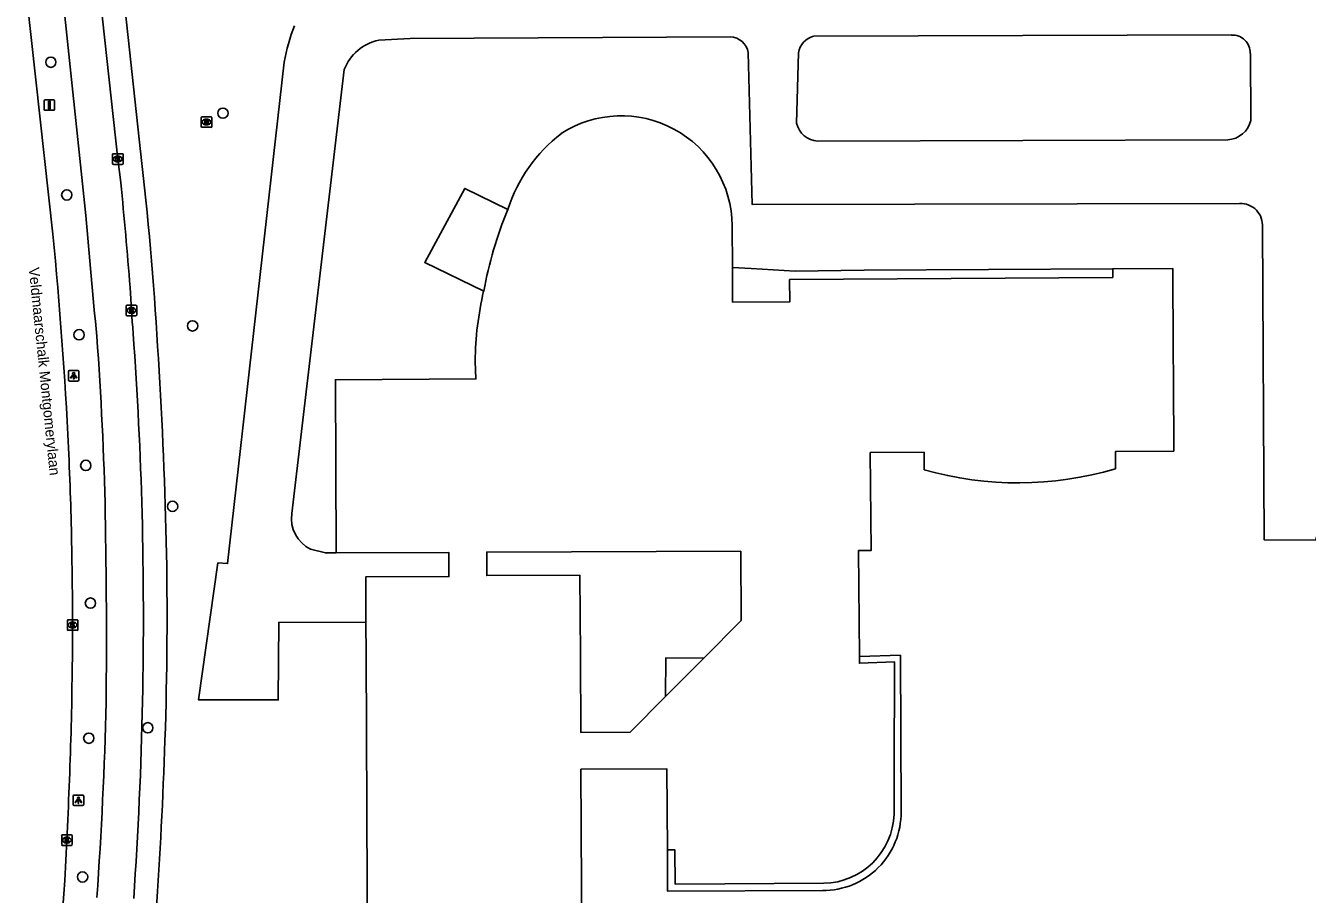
# Model space of a CAD drawing. Extents: x 161243 to 161752, y 384138 to 384885.
# Drawn here: x 161309.8 to 161431.6, y 384749.3 to 384831.8 of the extents above; entities that cross this region are included whole.
import ezdxf

# ---------------------------------------------------------------- set-up
doc = ezdxf.new("R2010")
doc.units = 0
for name, color, linetype in [('IMGEO_Boom', 7, 'Continuous'), ('IMGEO_Fietspad_gesloten', 7, 'Continuous'), ('IMGEO_Kolk', 7, 'Continuous'), ('IMGEO_Lichtpunt', 7, 'Continuous'), ('IMGEO_Openbare_ruimte_label', 7, 'Continuous'), ('IMGEO_OVBaan_gesloten', 7, 'Continuous'), ('IMGEO_Pand', 7, 'Continuous'), ('IMGEO_Pand_overbouw', 7, 'Continuous'), ('IMGEO_Rijbaan_lokaal_open', 7, 'Continuous'), ('IMGEO_Rioolput', 7, 'Continuous'), ('IMGEO_Verkeersbordpaal', 7, 'Continuous'), ('IMGEO_Voetpad_open', 7, 'Continuous')]:
    doc.layers.add(name, color=color, linetype=linetype)

msp = doc.modelspace()

# ---------------------------------------------------------------- linework, layer by layer
at = {"layer": 'IMGEO_Boom'}
for centre in [(161312.17, 384828.34), (161328.52, 384823.5), (161313.68, 384815.73), (161314.85, 384802.46), (161325.64, 384803.3), (161315.49, 384790.05), (161323.74, 384786.16), (161315.93, 384776.97), (161321.38, 384765.13), (161315.77, 384764.14), (161315.19, 384750.96)]:
    msp.add_circle(centre, 0.489, dxfattribs=at)
at = {"layer": 'IMGEO_Fietspad_gesloten'}
for points in [[(161313.17, 384835.74), (161315.49, 384813.78)], [(161318.81, 384816.9), (161318.53, 384819.14), (161316.84, 384834.53), (161316.67, 384836.2)]]:
    msp.add_lwpolyline(points, dxfattribs=at)
for centre, radius, start, end in [((160915.15, 384775.95), 405.73, 4.3808, 5.7921), ((162556.31, 384921.4), 1245.48, 184.95705, 185.48677), ((161677.13, 384828.87), 358.11, 183.51, 184.2089), ((160980.58, 384777.83), 336.85, 1.2915, 4.1673), ((160941.96, 384775.2), 379.02, 1.5556, 4.1435), ((160679.21, 384773.53), 638.24, 359.465, 1.06774), ((160926.58, 384775.69), 394.38, 358.8325, 1.4244), ((160906.46, 384777.92), 411.1, 355.9663, 358.557), ((160927.84, 384775.9), 393.13, 356.0636, 358.7984)]:
    msp.add_arc(centre, radius, start, end, dxfattribs=at)
at = {"layer": 'IMGEO_Kolk'}
for p, q in [((161318.03, 384818.71), (161318.03, 384819.57)), ((161318.11, 384819.64), (161318.96, 384819.64)), ((161318.52, 384819.42), (161318.54, 384819.42)), ((161318.54, 384818.86), (161318.52, 384818.86)), ((161319.03, 384819.57), (161319.03, 384818.71)), ((161318.96, 384818.64), (161318.11, 384818.64)), ((161319.34, 384804.33), (161319.34, 384805.18)), ((161319.41, 384805.26), (161320.26, 384805.26)), ((161320.26, 384804.26), (161319.41, 384804.26)), ((161319.85, 384804.48), (161319.82, 384804.48)), ((161319.83, 384805.04), (161319.85, 384805.04)), ((161320.34, 384805.18), (161320.34, 384804.33)), ((161313.74, 384774.46), (161313.74, 384775.31)), ((161313.82, 384775.39), (161314.67, 384775.39)), ((161314.23, 384775.17), (161314.26, 384775.17)), ((161314.74, 384775.31), (161314.74, 384774.46)), ((161314.67, 384774.39), (161313.82, 384774.39)), ((161314.25, 384774.61), (161314.23, 384774.61)), ((161313.2, 384754.03), (161313.2, 384754.88)), ((161313.27, 384754.96), (161314.12, 384754.96)), ((161313.68, 384754.74), (161313.71, 384754.74)), ((161313.71, 384754.18), (161313.68, 384754.18)), ((161314.2, 384754.88), (161314.2, 384754.03)), ((161314.12, 384753.96), (161313.27, 384753.96))]:
    msp.add_line(p, q, dxfattribs=at)
for points in [[(161318.03, 384818.71), (161318.03, 384819.57)], [(161318.11, 384819.64), (161318.96, 384819.64)], [(161318.35, 384819.34), (161318.48, 384819.34), (161318.48, 384819.19), (161318.6, 384819.34), (161318.77, 384819.34), (161318.62, 384819.19), (161318.78, 384818.94), (161318.62, 384818.94), (161318.54, 384819.11), (161318.48, 384819.04), (161318.48, 384818.94), (161318.35, 384818.94), (161318.35, 384819.34)], [(161319.03, 384819.57), (161319.03, 384818.71)], [(161318.96, 384818.64), (161318.11, 384818.64)], [(161319.34, 384804.33), (161319.34, 384805.18)], [(161319.41, 384805.26), (161320.26, 384805.26)], [(161320.26, 384804.26), (161319.41, 384804.26)], [(161319.66, 384804.96), (161319.78, 384804.96), (161319.78, 384804.81), (161319.91, 384804.96), (161320.08, 384804.96), (161319.93, 384804.81), (161320.08, 384804.56), (161319.93, 384804.56), (161319.85, 384804.72), (161319.78, 384804.66), (161319.78, 384804.56), (161319.66, 384804.56), (161319.66, 384804.96)], [(161320.34, 384805.18), (161320.34, 384804.33)], [(161313.74, 384774.46), (161313.74, 384775.31)], [(161313.82, 384775.39), (161314.67, 384775.39)], [(161314.06, 384775.09), (161314.19, 384775.09), (161314.19, 384774.94), (161314.32, 384775.09), (161314.48, 384775.09), (161314.33, 384774.94), (161314.49, 384774.69), (161314.33, 384774.69), (161314.25, 384774.85), (161314.19, 384774.78), (161314.19, 384774.69), (161314.06, 384774.69), (161314.06, 384775.09)], [(161314.74, 384775.31), (161314.74, 384774.46)], [(161314.67, 384774.39), (161313.82, 384774.39)], [(161313.2, 384754.03), (161313.2, 384754.88)], [(161313.27, 384754.96), (161314.12, 384754.96)], [(161313.52, 384754.66), (161313.64, 384754.66), (161313.64, 384754.5), (161313.77, 384754.66), (161313.93, 384754.66), (161313.79, 384754.51), (161313.94, 384754.26), (161313.79, 384754.26), (161313.7, 384754.42), (161313.64, 384754.35), (161313.64, 384754.26), (161313.52, 384754.26), (161313.52, 384754.66)], [(161314.2, 384754.88), (161314.2, 384754.03)], [(161314.12, 384753.96), (161313.27, 384753.96)]]:
    msp.add_lwpolyline(points, dxfattribs=at)
for centre, start, end in [((161318.11, 384819.57), 91.552, 178.448), ((161318.11, 384819.57), 91.552, 178.448), ((161318.11, 384818.72), 181.552, 268.448), ((161318.11, 384818.72), 181.552, 268.448), ((161318.96, 384819.57), 1.552, 88.448), ((161318.96, 384819.57), 1.552, 88.448), ((161318.96, 384818.72), 271.552, 358.448), ((161318.96, 384818.72), 271.552, 358.448), ((161319.41, 384805.18), 91.552, 178.448), ((161319.41, 384805.18), 91.552, 178.448), ((161319.41, 384804.33), 181.552, 268.448), ((161319.41, 384804.33), 181.552, 268.448), ((161320.26, 384805.18), 1.552, 88.448), ((161320.26, 384805.18), 1.552, 88.448), ((161320.26, 384804.33), 271.552, 358.448), ((161320.26, 384804.33), 271.552, 358.448), ((161313.82, 384775.31), 91.552, 178.448), ((161313.82, 384775.31), 91.552, 178.448), ((161314.67, 384775.31), 1.552, 88.448), ((161314.67, 384775.31), 1.552, 88.448), ((161313.82, 384774.46), 181.552, 268.448), ((161313.82, 384774.46), 181.552, 268.448), ((161314.67, 384774.46), 271.552, 358.448), ((161314.67, 384774.46), 271.552, 358.448), ((161313.27, 384754.88), 91.552, 178.448), ((161313.27, 384754.88), 91.552, 178.448), ((161314.12, 384754.88), 1.552, 88.448), ((161314.12, 384754.88), 1.552, 88.448), ((161313.27, 384754.03), 181.552, 268.448), ((161313.27, 384754.03), 181.552, 268.448), ((161314.12, 384754.03), 271.552, 358.448), ((161314.12, 384754.03), 271.552, 358.448)]:
    msp.add_arc(centre, 0.0765, start, end, dxfattribs=at)
for centre, major_axis, ratio, start_param, end_param in [((161318.52, 384819.14), (-0.387, 0.002), 0.722429, 4.712389, 7.853982), ((161318.54, 384819.14), (-0.39, 0.002), 0.717154, 1.570796, 4.712389), ((161319.82, 384804.76), (-0.387, 0.002), 0.722429, 4.712389, 7.853982), ((161319.85, 384804.76), (-0.39, 0.002), 0.717154, 1.570796, 4.712389), ((161314.23, 384774.89), (-0.387, 0.002), 0.722429, 4.712389, 7.853982), ((161314.25, 384774.89), (-0.39, 0.002), 0.717154, 1.570796, 4.712389), ((161313.68, 384754.46), (-0.387, 0.002), 0.722429, 4.712389, 7.853982), ((161313.71, 384754.46), (-0.39, 0.002), 0.717154, 1.570796, 4.712389)]:
    msp.add_ellipse(centre, major_axis=major_axis, ratio=ratio, start_param=start_param, end_param=end_param, dxfattribs=at)
at = {"layer": 'IMGEO_Lichtpunt'}
for p, q in [((161313.84, 384798.97), (161313.84, 384798.16)), ((161313.84, 384798.97), (161313.84, 384798.16)), ((161314.74, 384799.06), (161313.94, 384799.06)), ((161314.74, 384799.06), (161313.94, 384799.06)), ((161313.94, 384798.06), (161314.74, 384798.06)), ((161313.94, 384798.06), (161314.74, 384798.06)), ((161314.84, 384798.16), (161314.84, 384798.97)), ((161314.84, 384798.16), (161314.84, 384798.97)), ((161314.29, 384758.65), (161314.29, 384757.84)), ((161314.29, 384758.65), (161314.29, 384757.84)), ((161315.19, 384758.74), (161314.38, 384758.74)), ((161315.19, 384758.74), (161314.38, 384758.74)), ((161315.29, 384757.84), (161315.29, 384758.65)), ((161315.29, 384757.84), (161315.29, 384758.65)), ((161314.38, 384757.75), (161315.19, 384757.75)), ((161314.38, 384757.75), (161315.19, 384757.75))]:
    msp.add_line(p, q, dxfattribs=at)
for points in [[(161314.22, 384798.63), (161314.26, 384798.6), (161314.07, 384798.34), (161314.03, 384798.37), (161314.22, 384798.63)], [(161314.32, 384798.58), (161314.37, 384798.58), (161314.37, 384798.26), (161314.32, 384798.26), (161314.32, 384798.58)], [(161314.43, 384798.6), (161314.47, 384798.63), (161314.65, 384798.37), (161314.62, 384798.34), (161314.43, 384798.6)], [(161314.66, 384758.31), (161314.7, 384758.29), (161314.52, 384758.02), (161314.48, 384758.05), (161314.66, 384758.31)], [(161314.77, 384758.27), (161314.81, 384758.27), (161314.81, 384757.94), (161314.77, 384757.94), (161314.77, 384758.27)], [(161314.88, 384758.29), (161314.91, 384758.31), (161315.1, 384758.05), (161315.06, 384758.02), (161314.88, 384758.29)]]:
    msp.add_lwpolyline(points, dxfattribs=at)
for centre in [(161314.34, 384798.76), (161314.79, 384758.45)]:
    msp.add_circle(centre, 0.0994, dxfattribs=at)
for centre, start, end in [((161313.94, 384798.97), 90, 180), ((161313.94, 384798.97), 90, 180), ((161313.94, 384798.16), 180, 270), ((161313.94, 384798.16), 180, 270), ((161314.74, 384798.97), 0, 90), ((161314.74, 384798.97), 0, 90), ((161314.74, 384798.16), 270, 0), ((161314.74, 384798.16), 270, 360), ((161314.38, 384758.65), 90, 180), ((161314.38, 384758.65), 90, 180), ((161314.38, 384757.84), 180, 270), ((161314.38, 384757.84), 180, 270), ((161315.19, 384758.65), 0, 90), ((161315.19, 384758.65), 0, 90), ((161315.19, 384757.84), 270, 0), ((161315.19, 384757.84), 270, 360)]:
    msp.add_arc(centre, 0.0946, start, end, dxfattribs=at)
at = {"layer": 'IMGEO_OVBaan_gesloten'}
msp.add_lwpolyline([(161312.35, 384812.01), (161309.92, 384834.12), (161309.77, 384835.49)], dxfattribs=at)
for centre, radius, start, end in [((160897.12, 384771.42), 417.22, 2.7894, 5.5818), ((161036.76, 384777.78), 277.43, 0.8943, 2.8816), ((160613.83, 384769.87), 700.43, 0.41036, 1.00134), ((160483.55, 384781.48), 830.72, 358.84036, 359.54546), ((160408.63, 384795.21), 905.98, 357.42196, 358.0681), ((160902.05, 384775.09), 412.16, 354.2863, 357.1307)]:
    msp.add_arc(centre, radius, start, end, dxfattribs=at)
at = {"layer": 'IMGEO_Pand'}
for points in [[(161376.91, 384812.82), (161376.92, 384808.85), (161376.93, 384805.56), (161382.37, 384805.58), (161382.36, 384807.69), (161413.06, 384807.9), (161413.06, 384808.72), (161418.77, 384808.75), (161418.81, 384801.04), (161418.82, 384798.21), (161418.86, 384791.41), (161413.33, 384791.37), (161413.31, 384789.72)], [(161339.27, 384781.75), (161339.2, 384798.18), (161352.55, 384798.26), (161352.49, 384799.95)], [(161395.15, 384789.64), (161395.14, 384791.3), (161390.02, 384791.27), (161390.11, 384781.98), (161388.92, 384781.98), (161389, 384771.91), (161389, 384771.26), (161392.33, 384771.38), (161392.28, 384760.74), (161392.29, 384756.93)], [(161342.11, 384775.12), (161342.09, 384779.46), (161349.99, 384779.49), (161349.98, 384781.79), (161339.27, 384781.75)], [(161377.73, 384781.91), (161353.58, 384781.81), (161353.59, 384779.58), (161362.44, 384779.62), (161362.48, 384772.04), (161362.52, 384764.69), (161367.21, 384764.71), (161370.58, 384768.11), (161374.21, 384771.75), (161377.76, 384775.33), (161377.73, 384781.91)], [(161335.35, 384718.68), (161335.33, 384721.92), (161342.34, 384721.94), (161342.21, 384750), (161342.12, 384772.13), (161342.11, 384775.12)], [(161385.6, 384750.36), (161371.48, 384750.28), (161371.46, 384753.53), (161370.75, 384753.53), (161370.71, 384761.23), (161362.53, 384761.19), (161362.59, 384750), (161362.77, 384713.9)]]:
    msp.add_lwpolyline(points, dxfattribs=at)
for centre, radius, start, end in [((161366.37, 384812.71), 10.54, 0.5841, 122.7433), ((161369.64, 384809.87), 14.74, 127.458, 162.338), ((161390.76, 384799.72), 38.09, 157.4254, 169.6197), ((161383.35, 384799.57), 30.87, 166.8502, 179.2949), ((161404.09, 384821.23), 32.84, 254.2021, 286.309), ((161385.49, 384757.16), 6.8, 270.9846, 358.0908)]:
    msp.add_arc(centre, radius, start, end, dxfattribs=at)
at = {"layer": 'IMGEO_Pand_overbouw'}
for points in [[(161355.59, 384814.35), (161351.5, 384816.36), (161347.7, 384809.31), (161353.3, 384806.59)], [(161392.95, 384757.16), (161392.89, 384772.02), (161389, 384771.91), (161389, 384771.26), (161392.33, 384771.38), (161392.28, 384760.74), (161392.29, 384756.93)], [(161385.6, 384750.36), (161371.48, 384750.28), (161371.46, 384753.53), (161370.75, 384753.53), (161370.75, 384750), (161370.75, 384749.62), (161385.47, 384749.68)]]:
    msp.add_lwpolyline(points, dxfattribs=at)
for points in [[(161413.06, 384808.72), (161389.43, 384808.58), (161382.89, 384808.51), (161378.71, 384808.75), (161376.92, 384808.85), (161376.93, 384805.56), (161382.37, 384805.58), (161382.36, 384807.69), (161413.06, 384807.9)], [(161374.21, 384771.75), (161370.6, 384771.77), (161370.58, 384768.11)]]:
    msp.add_lwpolyline(points, close=True, dxfattribs=at)
for centre, radius, start, end in [((161390.76, 384799.72), 38.09, 157.4254, 169.6197), ((161385.56, 384757.07), 7.39, 269.3316, 0.7143), ((161385.49, 384757.16), 6.8, 270.9846, 358.0908)]:
    msp.add_arc(centre, radius, start, end, dxfattribs=at)
at = {"layer": 'IMGEO_Rijbaan_lokaal_open'}
for points in [[(161384.65, 384830.81), (161424.34, 384830.93)], [(161343.33, 384830.42), (161346.31, 384830.59), (161376.74, 384830.76)], [(161378.43, 384829.25), (161378.79, 384814.84), (161425.12, 384814.93)], [(161383.02, 384822.54), (161383.19, 384829.23)], [(161426.14, 384829.18), (161426.18, 384822.81)], [(161334.34, 384828.34), (161328.96, 384780.72), (161328.05, 384780.79), (161326.21, 384767.78), (161333.77, 384767.78), (161333.84, 384775.15), (161342.11, 384775.12)], [(161335.06, 384785.47), (161340.05, 384827.65)], [(161423.99, 384820.96), (161385.03, 384820.84)], [(161427.28, 384812.66), (161427.44, 384782.98), (161432.34, 384782.95), (161436.96, 384794.98)], [(161339.27, 384781.75), (161338.26, 384781.74), (161336.85, 384782.08)]]:
    msp.add_lwpolyline(points, dxfattribs=at)
for centre, radius, start, end in [((161352.94, 384824.96), 18.9, 158.7607, 169.6938), ((161424.43, 384829.22), 1.7, 358.5733, 92.9822), ((161344.21, 384826.05), 4.46, 101.483, 159.007), ((161376.62, 384828.92), 1.84, 10.4144, 86.4108), ((161385.15, 384828.88), 1.99, 104.6612, 169.8296), ((161385.19, 384823.06), 2.23, 193.6365, 265.9317), ((161423.85, 384823.35), 2.39, 273.2264, 347.038), ((161425.2, 384812.84), 2.09, 355.0745, 92.1601), ((161338.29, 384785.01), 3.26, 171.8245, 243.8427)]:
    msp.add_arc(centre, radius, start, end, dxfattribs=at)
at = {"layer": 'IMGEO_Rioolput'}
for p, q in [((161326.45, 384822.23), (161326.45, 384823.08)), ((161326.53, 384823.16), (161327.38, 384823.16)), ((161326.94, 384822.94), (161326.96, 384822.94)), ((161326.96, 384822.38), (161326.94, 384822.38)), ((161327.45, 384823.08), (161327.45, 384822.23)), ((161327.38, 384822.16), (161326.53, 384822.16))]:
    msp.add_line(p, q, dxfattribs=at)
for points in [[(161326.45, 384822.23), (161326.45, 384823.08)], [(161326.53, 384823.16), (161327.38, 384823.16)], [(161327.04, 384822.85), (161326.79, 384822.86), (161326.79, 384822.46)], [(161326.79, 384822.46), (161326.91, 384822.46), (161326.91, 384822.62), (161326.92, 384822.62)], [(161326.97, 384822.78), (161326.91, 384822.78), (161326.91, 384822.69)], [(161326.91, 384822.69), (161326.96, 384822.69)], [(161326.97, 384822.59), (161327.04, 384822.46), (161327.18, 384822.46), (161327.12, 384822.58)], [(161327.45, 384823.08), (161327.45, 384822.23)], [(161327.38, 384822.16), (161326.53, 384822.16)]]:
    msp.add_lwpolyline(points, dxfattribs=at)
for centre, radius, start, end in [((161326.53, 384823.08), 0.0765, 91.552, 178.448), ((161326.53, 384823.08), 0.0765, 91.552, 178.448), ((161326.92, 384822.57), 0.0533, 26.0293, 88.6989), ((161326.95, 384822.88), 0.19, 274.7715, 282.9687), ((161326.97, 384822.68), 0.0964, 77.0061, 93.1865), ((161326.99, 384822.74), 0.0378, 276.6634, 79.6772), ((161327.04, 384822.74), 0.109, 350.3612, 89.416), ((161327.04, 384822.74), 0.112, 277.5842, 350.9817), ((161327.02, 384822.53), 0.108, 29.5134, 73.7905), ((161327.38, 384823.08), 0.0765, 1.552, 88.448), ((161327.38, 384823.08), 0.0765, 1.552, 88.448), ((161326.53, 384822.23), 0.0765, 181.552, 268.448), ((161326.53, 384822.23), 0.0765, 181.552, 268.448), ((161327.38, 384822.23), 0.0765, 271.552, 358.448), ((161327.38, 384822.23), 0.0765, 271.552, 358.448)]:
    msp.add_arc(centre, radius, start, end, dxfattribs=at)
for centre, major_axis, ratio, start_param, end_param in [((161326.94, 384822.66), (-0.387, 0.002), 0.722429, 4.712389, 7.853982), ((161326.96, 384822.66), (-0.39, 0.002), 0.717154, 1.570796, 4.712389)]:
    msp.add_ellipse(centre, major_axis=major_axis, ratio=ratio, start_param=start_param, end_param=end_param, dxfattribs=at)
at = {"layer": 'IMGEO_Verkeersbordpaal'}
for p, q in [((161311.63, 384824.77), (161312.42, 384824.77)), ((161312.42, 384824.77), (161311.63, 384824.77)), ((161311.53, 384823.87), (161311.53, 384824.67)), ((161311.53, 384824.67), (161311.53, 384823.87)), ((161312.42, 384823.77), (161311.63, 384823.77)), ((161311.63, 384823.77), (161312.42, 384823.77)), ((161312.52, 384824.67), (161312.52, 384823.87)), ((161312.52, 384823.87), (161312.52, 384824.67))]:
    msp.add_line(p, q, dxfattribs=at)
msp.add_lwpolyline([(161311.95, 384824.65), (161312.1, 384824.65), (161312.1, 384823.9), (161311.95, 384823.9), (161311.95, 384824.65)], dxfattribs=at)
for centre, start, end in [((161311.63, 384824.67), 90, 180), ((161311.63, 384824.67), 90, 180), ((161312.42, 384824.67), 0, 90), ((161312.42, 384824.67), 360, 90), ((161311.63, 384823.87), 180, 270), ((161311.63, 384823.87), 180, 270), ((161312.42, 384823.87), 270, 0), ((161312.42, 384823.87), 270, 0)]:
    msp.add_arc(centre, 0.1, start, end, dxfattribs=at)
at = {"layer": 'IMGEO_Voetpad_open'}
msp.add_lwpolyline([(161319.11, 384834.5), (161320.7, 384819.87)], dxfattribs=at)
for centre, radius, start, end in [((160993.16, 384781.86), 329.73, 3.3868, 6.6207), ((160896.08, 384773.42), 427.15, 1.2616, 3.7479), ((160979.45, 384775.58), 343.76, 358.0585, 1.2076), ((160885.64, 384778.18), 437.6, 355.9868, 358.1341)]:
    msp.add_arc(centre, radius, start, end, dxfattribs=at)

# ---------------------------------------------------------------- texts
at = {"layer": 'IMGEO_Openbare_ruimte_label'}
msp.add_text('Veldmaarschalk Montgomerylaan', height=1, rotation=275.8414, dxfattribs=at).set_placement((161310.06, 384808.8))

doc.saveas('drawing.dxf')
